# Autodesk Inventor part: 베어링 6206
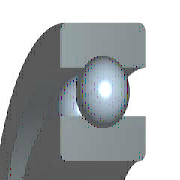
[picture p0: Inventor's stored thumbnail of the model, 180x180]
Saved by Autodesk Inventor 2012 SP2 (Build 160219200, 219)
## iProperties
Created: 2009-02
Part Number: 베어링 6206
Material: Steel, Mild
Description: 깊은 그루브 볼 베어링
Document SubType Name: Modeling
Standard: KS B 2023
Designer: KYOUNG IL JANG
Standards Organization: KS
Language: ko-KR
Size Designation: 6206 - 30 x 62 x 16
Categories: <MemberInstance><Categories><Category DisplayName="샤프트 부품" InternalName="7f7aeb1f-a693-4053-b835-cee3144e0d98" Mnemonic="SHFT"><Category DisplayName="베어링" Inter
Density: 1 g/cm^3
Company: 한국ATC센터
IsCustomPart: 0
Author: KYOUNG IL JANG
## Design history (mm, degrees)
revolve "본체" stored, may be unused: angle "d6" = 90 deg
revolve "볼" stored, may be unused: angle "d7" = 90 deg
pattern_circular "IDS_ARRAYBALL[SIMPL:T]" dims angle "d3" = 360 deg
body "Solid1"
sketch "스케치" dims "d0" = 8.32 (= -0.26 x WD + 0.26 x BD)
  geometry: L1 (3.84, 23)-(12.16, 23); L2 (8, 23)-(8, 18.84); L3 (8, 23)-(8, 27.16); L4 (4.909, 20.216)-(0, 20.216); L5 (0, 15)-(16, 15); L6 (4.909, 25.784)-(0, 25.784); L7 (0, 31)-(16, 31); L8 (16, 15)-(16, 20.216); L9 (11.091, 20.216)-(16, 20.216); L10 (11.091, 25.784)-(16, 25.784); L11 (16, 31)-(16, 25.784); L12 (-1.4, 0)-(8.4, 0) reference; L13 (0, -0.3)-(0, 5.3) reference
  constraints: 22 end point, 4 point on line, 2 collinear, 2 perpendicular, 2 symmetric about line, 1 midpoint, 1 parallel, 14 other
  dimensions: "d9" = 30 diameter of L5 L12 (= WD); "d11" = 62 diameter of L7 L12 (= BD); "d12" = 16 distance between parallel lines of L8 L13 (= KB); "d13" = 40.432 diameter of L9 L12 (= 0.326 x BD + 0.674 x WD)
fillet "모깎기1" dims "d1" = 1 (= KRS)
other parameters: "WD" = 30 [user parameter; used in 5 equation terms], "BD" = 62 [user parameter; used in 5 equation terms], "KB" = 16 [user parameter; used in 1 equation term], "KRS" = 1 [user parameter; used in 1 equation term], "d4" = 0, "d5" = 0, "d8" = 0, "d14" = 0, "d15" = 0, "BBA" = 0 [user parameter], "BC0" = 1.12e+07 [user parameter], "BC" = 1.95e+07 [user parameter], "BR" = 31 (= 0.5 x BD) [user parameter], "WR" = 15 (= 0.5 x WD) [user parameter]
